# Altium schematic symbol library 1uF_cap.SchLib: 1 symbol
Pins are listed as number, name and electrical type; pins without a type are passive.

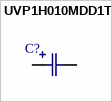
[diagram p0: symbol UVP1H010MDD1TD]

## UVP1H010MDD1TD
designator C?  (value not drawn)
1 uF, 50V, 20% Capacitor; Vendor: Nichicon; Built_By: EMA_UL_Team; C: Copyright (C) 2015 Accelerated Designs. All rights reserved
footprint U1-E
pins: 1, 2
